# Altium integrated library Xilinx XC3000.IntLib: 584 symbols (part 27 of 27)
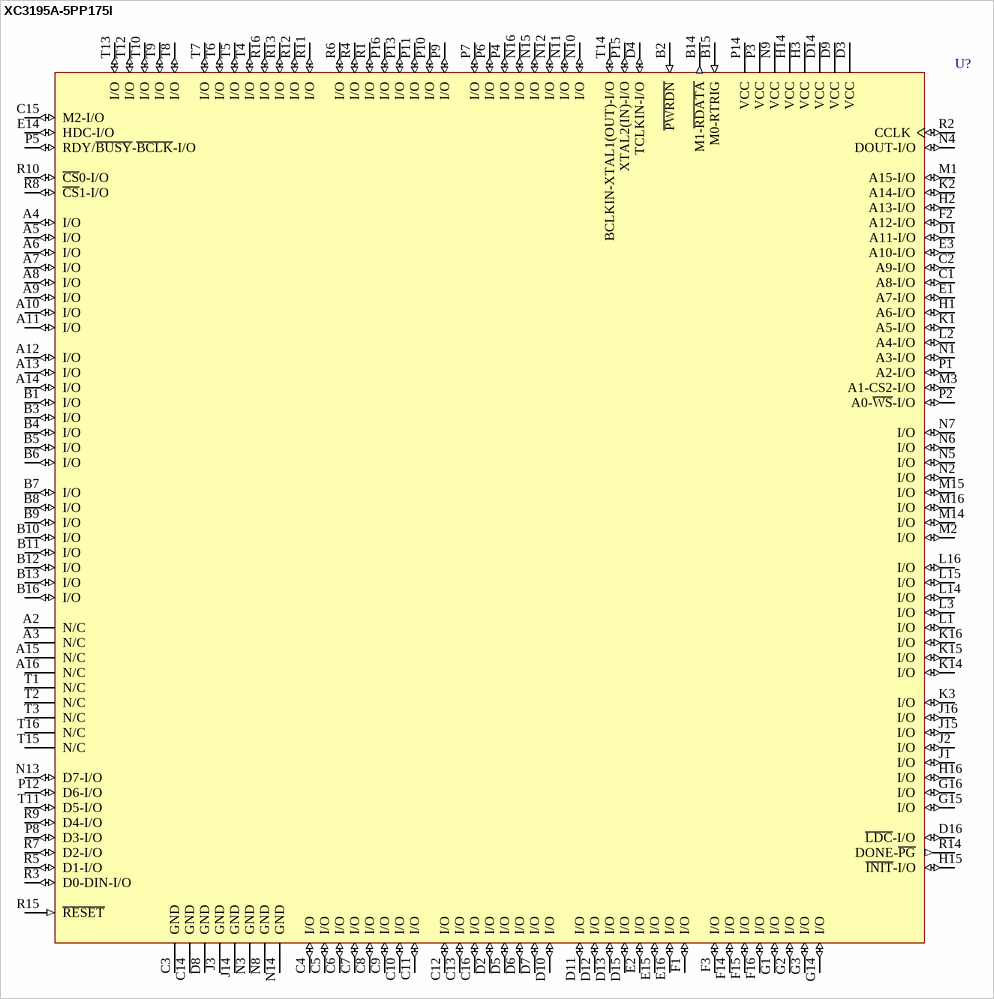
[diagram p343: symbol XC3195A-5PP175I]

## XC3195A-5PP175I
designator U?
Logic Cell Array with 484 CLBs, with 144 I/O Pins, 175-Pin PGA, Industrial Grade; ComponentAvailability: Not for New Design
footprint PP175 (PGA, 175-Leads, Body 42x42mm, Pitch 2.54mm)
3D model XC3195A-PP175 (175-Pin Plastic Pin Grid Array (PP175))
pins: A2 N/C, A3 N/C, A4 I/O (io), A5 I/O (io), A6 I/O (io), A7 I/O (io), A8 I/O (io), A9 I/O (io), A10 I/O (io), A11 I/O (io), A12 I/O (io), A13 I/O (io), A14 I/O (io), A15 N/C, A16 N/C, B1 I/O (io), B2 ~{PWRDN} (in), B3 I/O (io), B4 I/O (io), B5 I/O (io), B6 I/O (io), B7 I/O (io), B8 I/O (io), B9 I/O (io), B10 I/O (io), B11 I/O (io), B12 I/O (io), B13 I/O (io), B14 M1-~{RDATA} (out), B15 M0-RTRIG (in), B16 I/O (io), C1 A8-I/O (io), C2 A9-I/O (io), C3 GND (power), C4 I/O (io), C5 I/O (io), C6 I/O (io), C7 I/O (io), C8 I/O (io), C9 I/O (io), C10 I/O (io), C11 I/O (io), C12 I/O (io), C13 I/O (io), C14 GND (power), C15 M2-I/O (io), C16 I/O (io), D1 A11-I/O (io), D2 I/O (io), D3 VCC (power), D4 TCLKIN-I/O (io), D5 I/O (io), D6 I/O (io), D7 I/O (io), D8 GND (power), D9 VCC (power), D10 I/O (io), D11 I/O (io), D12 I/O (io), D13 I/O (io), D14 VCC (power), D15 I/O (io), D16 ~{LDC}-I/O (io), E1 A7-I/O (io), E2 I/O (io), E3 A10-I/O (io), E14 HDC-I/O (io), E15 I/O (io), E16 I/O (io), F1 I/O (io), F2 A12-I/O (io), F3 I/O (io), F14 I/O (io), F15 I/O (io), F16 I/O (io), G1 I/O (io), G2 I/O (io), G3 I/O (io), G14 I/O (io), G15 I/O (io), G16 I/O (io), H1 A6-I/O (io), H2 A13-I/O (io), H3 VCC (power), H14 VCC (power), H15 ~{INIT}-I/O (io), H16 I/O (io), J1 I/O (io), J2 I/O (io), J3 GND (power), J14 GND (power), J15 I/O (io), J16 I/O (io), K1 A5-I/O (io), K2 A14-I/O (io), K3 I/O (io), K14 I/O (io), K15 I/O (io), K16 I/O (io), L1 I/O (io), L2 A4-I/O (io), L3 I/O (io), L14 I/O (io), L15 I/O (io), L16 I/O (io), M1 A15-I/O (io), M2 I/O (io), M3 A1-CS2-I/O (io), M14 I/O (io), M15 I/O (io), M16 I/O (io), N1 A3-I/O (io), N2 I/O (io), N3 GND (power), N4 DOUT-I/O (io), N5 I/O (io), N6 I/O (io), N7 I/O (io), N8 GND (power), N9 VCC (power), N10 I/O (io), N11 I/O (io), N12 I/O (io), N13 D7-I/O (io), N14 GND (power), N15 I/O (io), N16 I/O (io), P1 A2-I/O (io), P2 A0-~{WS}-I/O (io), P3 VCC (power), P4 I/O (io), P5 RDY/~{BUSY}-~{BCLK}-I/O (io), P6 I/O (io), P7 I/O (io), P8 D3-I/O (io), P9 I/O (io), P10 I/O (io), P11 I/O (io), P12 D6-I/O (io), P13 I/O (io), P14 VCC (power), P15 XTAL2(IN)-I/O (io), P16 I/O (io), R1 I/O (io), R2 CCLK (io), R3 D0-DIN-I/O (io), R4 I/O (io), R5 D1-I/O (io), R6 I/O (io), R7 D2-I/O (io), R8 ~{CS}1-I/O (io), R9 D4-I/O (io), R10 ~{CS}0-I/O (io), R11 I/O (io), R12 I/O (io), R13 I/O (io), R14 DONE-~{PG} (out), R15 ~{RESET} (in), R16 I/O (io), T1 N/C, T2 N/C, T3 N/C, T4 I/O (io), T5 I/O (io), T6 I/O (io), T7 I/O (io), T8 I/O (io), T9 I/O (io), T10 I/O (io), T11 D5-I/O (io), T12 I/O (io), T13 I/O (io), T14 BCLKIN-XTAL1(OUT)-I/O (io), T15 N/C, T16 N/C

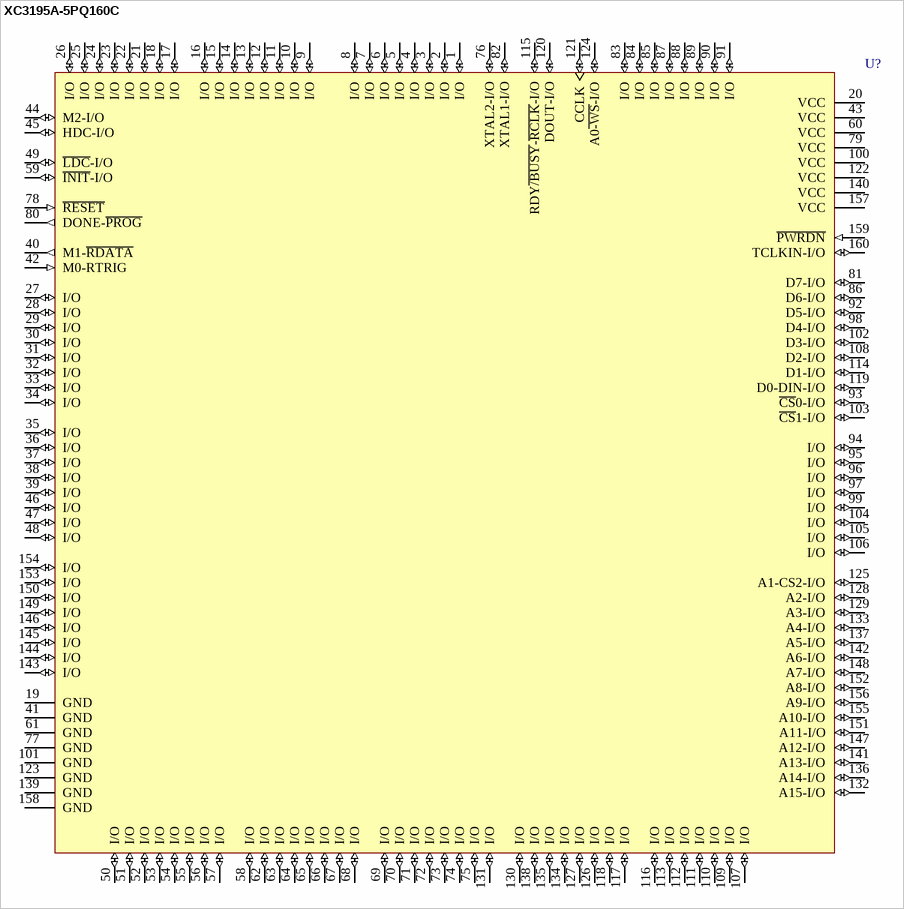
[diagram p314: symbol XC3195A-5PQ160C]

## XC3195A-5PQ160C
designator U?
Logic Cell Array with 484 CLBs, with 138 I/O Pins, 160-Pin PQFP, Commercial Grade; ComponentAvailability: Not for New Design
footprint PQ160_N (QFP, 160-Leads, Body 28 x 28mm, Pitch 0.65mm, IPC Medium Density)
footprint PQ160_L (QFP, 160-Leads, Body 28 x 28mm, Pitch 0.65mm, IPC High Density)
footprint PQ160_M (QFP, 160-Leads, Body 28 x 28mm, Pitch 0.65mm, IPC Low Density)
3D model XC3195A-PQ160 (160-Pin Plastic Quad Flat Pack (PQ160))
pins: 1 I/O (io), 2 I/O (io), 3 I/O (io), 4 I/O (io), 5 I/O (io), 6 I/O (io), 7 I/O (io), 8 I/O (io), 9 I/O (io), 10 I/O (io), 11 I/O (io), 12 I/O (io), 13 I/O (io), 14 I/O (io), 15 I/O (io), 16 I/O (io), 17 I/O (io), 18 I/O (io), 19 GND (power), 20 VCC (power), 21 I/O (io), 22 I/O (io), 23 I/O (io), 24 I/O (io), 25 I/O (io), 26 I/O (io), 27 I/O (io), 28 I/O (io), 29 I/O (io), 30 I/O (io), 31 I/O (io), 32 I/O (io), 33 I/O (io), 34 I/O (io), 35 I/O (io), 36 I/O (io), 37 I/O (io), 38 I/O (io), 39 I/O (io), 40 M1-~{RDATA} (out), 41 GND (power), 42 M0-RTRIG (in), 43 VCC (power), 44 M2-I/O (io), 45 HDC-I/O (io), 46 I/O (io), 47 I/O (io), 48 I/O (io), 49 ~{LDC}-I/O (io), 50 I/O (io), 51 I/O (io), 52 I/O (io), 53 I/O (io), 54 I/O (io), 55 I/O (io), 56 I/O (io), 57 I/O (io), 58 I/O (io), 59 ~{INIT}-I/O (io), 60 VCC (power), 61 GND (power), 62 I/O (io), 63 I/O (io), 64 I/O (io), 65 I/O (io), 66 I/O (io), 67 I/O (io), 68 I/O (io), 69 I/O (io), 70 I/O (io), 71 I/O (io), 72 I/O (io), 73 I/O (io), 74 I/O (io), 75 I/O (io), 76 XTAL2-I/O (io), 77 GND (power), 78 ~{RESET} (in), 79 VCC (power), 80 DONE-~{PROG} (out), 81 D7-I/O (io), 82 XTAL1-I/O (io), 83 I/O (io), 84 I/O (io), 85 I/O (io), 86 D6-I/O (io), 87 I/O (io), 88 I/O (io), 89 I/O (io), 90 I/O (io), 91 I/O (io), 92 D5-I/O (io), 93 ~{CS}0-I/O (io), 94 I/O (io), 95 I/O (io), 96 I/O (io), 97 I/O (io), 98 D4-I/O (io), 99 I/O (io), 100 VCC (power), 101 GND (power), 102 D3-I/O (io), 103 ~{CS}1-I/O (io), 104 I/O (io), 105 I/O (io), 106 I/O (io), 107 I/O (io), 108 D2-I/O (io), 109 I/O (io), 110 I/O (io), 111 I/O (io), 112 I/O (io), 113 I/O (io), 114 D1-I/O (io), 115 RDY~{/BUSY}-~{RCLK}-I/O (io), 116 I/O (io), 117 I/O (io), 118 I/O (io), 119 D0-DIN-I/O (io), 120 DOUT-I/O (io), 121 CCLK (io), 122 VCC (power), 123 GND (power), 124 A0~{-WS}-I/O (io), 125 A1-CS2-I/O (io), 126 I/O (io), 127 I/O (io), 128 A2-I/O (io), 129 A3-I/O (io), 130 I/O (io), 131 I/O (io), 132 A15-I/O (io), 133 A4-I/O (io), 134 I/O (io), 135 I/O (io), 136 A14-I/O (io), 137 A5-I/O (io), 138 I/O (io), 139 GND (power), 140 VCC (power), 141 A13-I/O (io), 142 A6-I/O (io), 143 I/O (io), 144 I/O (io), 145 I/O (io), 146 I/O (io), 147 A12-I/O (io), 148 A7-I/O (io), 149 I/O (io), 150 I/O (io), 151 A11-I/O (io), 152 A8-I/O (io), 153 I/O (io), 154 I/O (io), 155 A10-I/O (io), 156 A9-I/O (io), 157 VCC (power), 158 GND (power), 159 ~{PWRDN} (in), 160 TCLKIN-I/O (io)

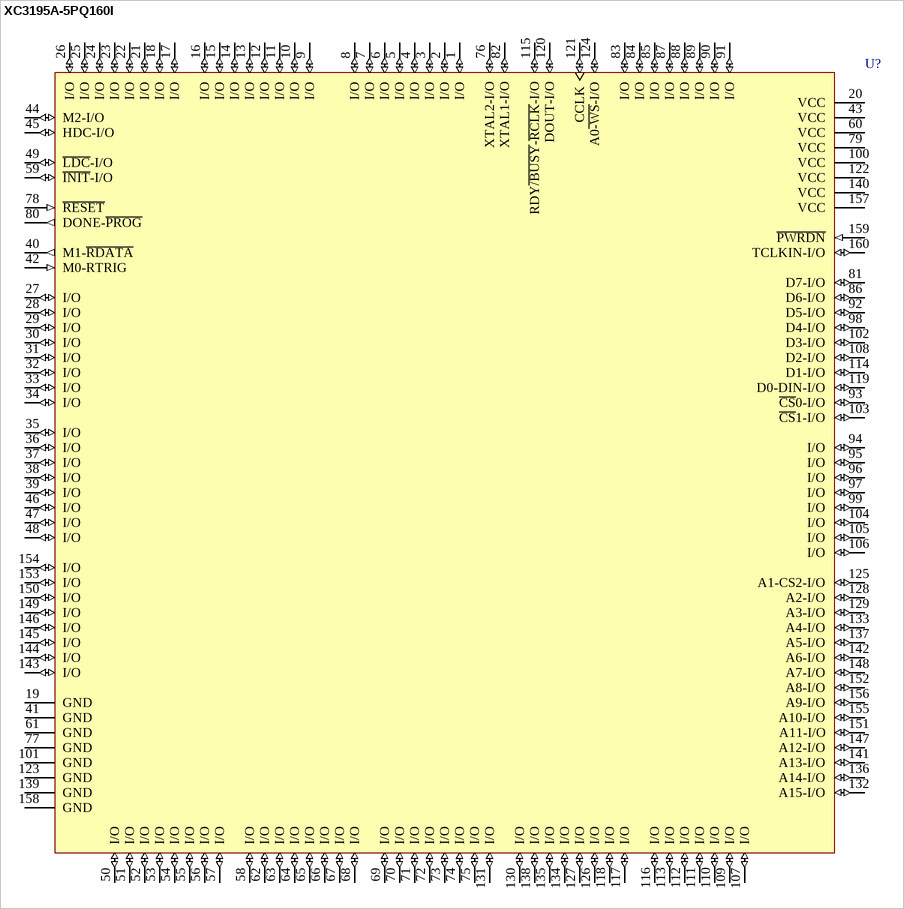
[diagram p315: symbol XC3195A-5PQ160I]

## XC3195A-5PQ160I
designator U?
Logic Cell Array with 484 CLBs, with 138 I/O Pins, 160-Pin PQFP, Industrial Grade; ComponentAvailability: Not for New Design
footprint PQ160_N (QFP, 160-Leads, Body 28 x 28mm, Pitch 0.65mm, IPC Medium Density)
footprint PQ160_L (QFP, 160-Leads, Body 28 x 28mm, Pitch 0.65mm, IPC High Density)
footprint PQ160_M (QFP, 160-Leads, Body 28 x 28mm, Pitch 0.65mm, IPC Low Density)
3D model XC3195A-PQ160 (160-Pin Plastic Quad Flat Pack (PQ160))
pins: 1 I/O (io), 2 I/O (io), 3 I/O (io), 4 I/O (io), 5 I/O (io), 6 I/O (io), 7 I/O (io), 8 I/O (io), 9 I/O (io), 10 I/O (io), 11 I/O (io), 12 I/O (io), 13 I/O (io), 14 I/O (io), 15 I/O (io), 16 I/O (io), 17 I/O (io), 18 I/O (io), 19 GND (power), 20 VCC (power), 21 I/O (io), 22 I/O (io), 23 I/O (io), 24 I/O (io), 25 I/O (io), 26 I/O (io), 27 I/O (io), 28 I/O (io), 29 I/O (io), 30 I/O (io), 31 I/O (io), 32 I/O (io), 33 I/O (io), 34 I/O (io), 35 I/O (io), 36 I/O (io), 37 I/O (io), 38 I/O (io), 39 I/O (io), 40 M1-~{RDATA} (out), 41 GND (power), 42 M0-RTRIG (in), 43 VCC (power), 44 M2-I/O (io), 45 HDC-I/O (io), 46 I/O (io), 47 I/O (io), 48 I/O (io), 49 ~{LDC}-I/O (io), 50 I/O (io), 51 I/O (io), 52 I/O (io), 53 I/O (io), 54 I/O (io), 55 I/O (io), 56 I/O (io), 57 I/O (io), 58 I/O (io), 59 ~{INIT}-I/O (io), 60 VCC (power), 61 GND (power), 62 I/O (io), 63 I/O (io), 64 I/O (io), 65 I/O (io), 66 I/O (io), 67 I/O (io), 68 I/O (io), 69 I/O (io), 70 I/O (io), 71 I/O (io), 72 I/O (io), 73 I/O (io), 74 I/O (io), 75 I/O (io), 76 XTAL2-I/O (io), 77 GND (power), 78 ~{RESET} (in), 79 VCC (power), 80 DONE-~{PROG} (out), 81 D7-I/O (io), 82 XTAL1-I/O (io), 83 I/O (io), 84 I/O (io), 85 I/O (io), 86 D6-I/O (io), 87 I/O (io), 88 I/O (io), 89 I/O (io), 90 I/O (io), 91 I/O (io), 92 D5-I/O (io), 93 ~{CS}0-I/O (io), 94 I/O (io), 95 I/O (io), 96 I/O (io), 97 I/O (io), 98 D4-I/O (io), 99 I/O (io), 100 VCC (power), 101 GND (power), 102 D3-I/O (io), 103 ~{CS}1-I/O (io), 104 I/O (io), 105 I/O (io), 106 I/O (io), 107 I/O (io), 108 D2-I/O (io), 109 I/O (io), 110 I/O (io), 111 I/O (io), 112 I/O (io), 113 I/O (io), 114 D1-I/O (io), 115 RDY~{/BUSY}-~{RCLK}-I/O (io), 116 I/O (io), 117 I/O (io), 118 I/O (io), 119 D0-DIN-I/O (io), 120 DOUT-I/O (io), 121 CCLK (io), 122 VCC (power), 123 GND (power), 124 A0~{-WS}-I/O (io), 125 A1-CS2-I/O (io), 126 I/O (io), 127 I/O (io), 128 A2-I/O (io), 129 A3-I/O (io), 130 I/O (io), 131 I/O (io), 132 A15-I/O (io), 133 A4-I/O (io), 134 I/O (io), 135 I/O (io), 136 A14-I/O (io), 137 A5-I/O (io), 138 I/O (io), 139 GND (power), 140 VCC (power), 141 A13-I/O (io), 142 A6-I/O (io), 143 I/O (io), 144 I/O (io), 145 I/O (io), 146 I/O (io), 147 A12-I/O (io), 148 A7-I/O (io), 149 I/O (io), 150 I/O (io), 151 A11-I/O (io), 152 A8-I/O (io), 153 I/O (io), 154 I/O (io), 155 A10-I/O (io), 156 A9-I/O (io), 157 VCC (power), 158 GND (power), 159 ~{PWRDN} (in), 160 TCLKIN-I/O (io)

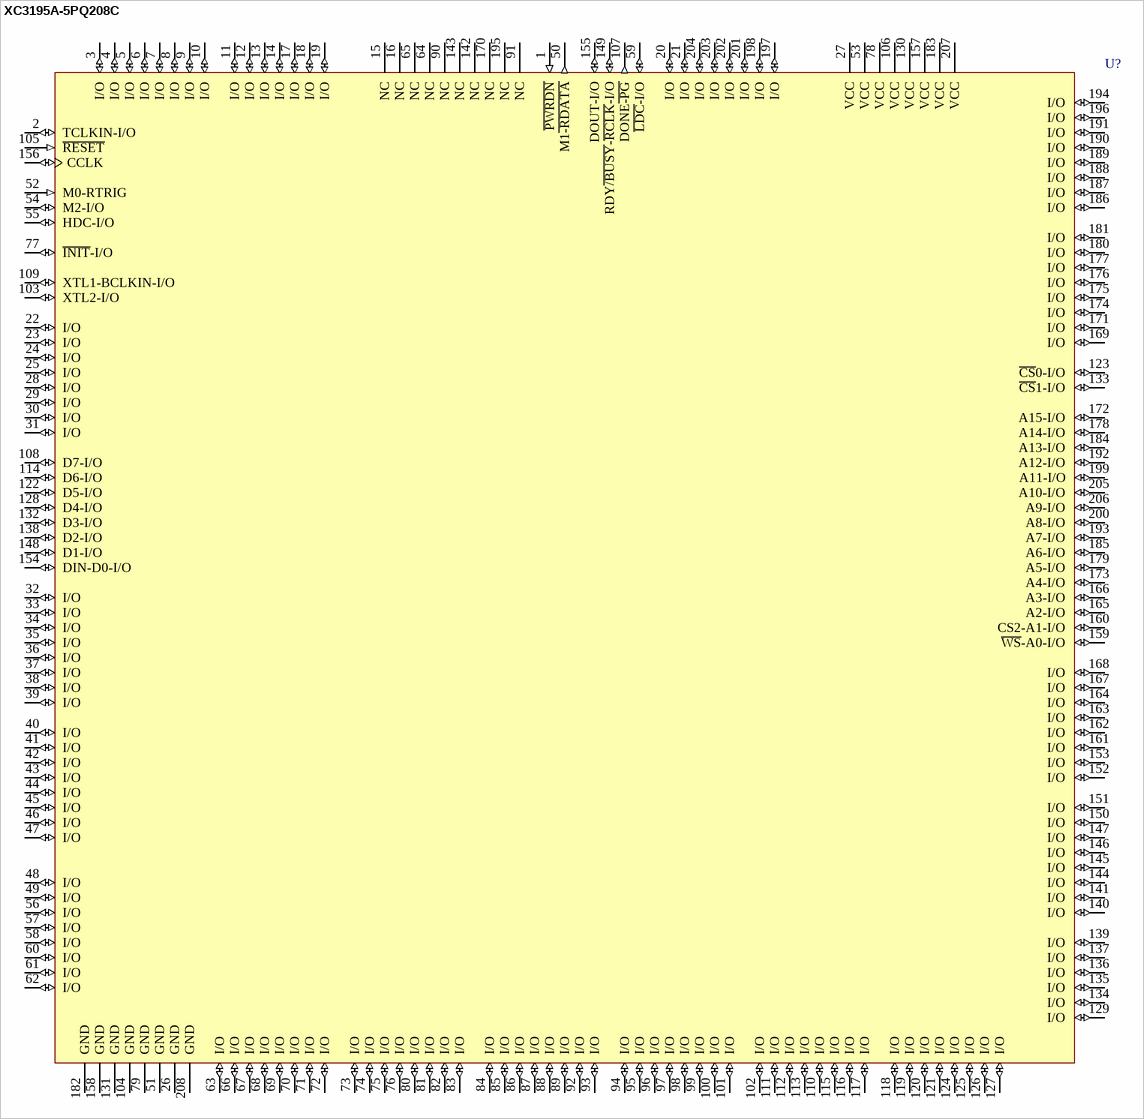
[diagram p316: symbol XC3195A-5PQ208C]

## XC3195A-5PQ208C
designator U?
Logic Cell Array with 484 CLBs, with 176 I/O Pins, 208-Pin PQFP, Commercial Grade; ComponentAvailability: Not for New Design
footprint PQ208_N (Shrink QFP, 208-Leads, Body 28x28mm, Pitch 0.5mm, IPC Medium Density)
footprint PQ208_L (Shrink QFP, 208-Leads, Body 28x28mm, Pitch 0.5mm, IPC High Density)
footprint PQ208_M (Shrink QFP, 208-Leads, Body 28x28mm, Pitch 0.5mm, IPC Low Density)
3D model XC3195A-PQ208 (208-Pin Plastic Quad Flat Pack (PQ208))
pins: 1 ~{PWRDN} (in), 2 TCLKIN-I/O (io), 3 I/O (io), 4 I/O (io), 5 I/O (io), 6 I/O (io), 7 I/O (io), 8 I/O (io), 9 I/O (io), 10 I/O (io), 11 I/O (io), 12 I/O (io), 13 I/O (io), 14 I/O (io), 15 NC, 16 NC, 17 I/O (io), 18 I/O (io), 19 I/O (io), 20 I/O (io), 21 I/O (io), 22 I/O (io), 23 I/O (io), 24 I/O (io), 25 I/O (io), 26 GND (power), 27 VCC (power), 28 I/O (io), 29 I/O (io), 30 I/O (io), 31 I/O (io), 32 I/O (io), 33 I/O (io), 34 I/O (io), 35 I/O (io), 36 I/O (io), 37 I/O (io), 38 I/O (io), 39 I/O (io), 40 I/O (io), 41 I/O (io), 42 I/O (io), 43 I/O (io), 44 I/O (io), 45 I/O (io), 46 I/O (io), 47 I/O (io), 48 I/O (io), 49 I/O (io), 50 M1~{-RDATA} (out), 51 GND (power), 52 M0-RTRIG (in), 53 VCC (power), 54 M2-I/O (io), 55 HDC-I/O (io), 56 I/O (io), 57 I/O (io), 58 I/O (io), 59 ~{LDC}-I/O (io), 60 I/O (io), 61 I/O (io), 62 I/O (io), 63 I/O (io), 64 NC, 65 NC, 66 I/O (io), 67 I/O (io), 68 I/O (io), 69 I/O (io), 70 I/O (io), 71 I/O (io), 72 I/O (io), 73 I/O (io), 74 I/O (io), 75 I/O (io), 76 I/O (io), 77 ~{INIT}-I/O (io), 78 VCC (power), 79 GND (power), 80 I/O (io), 81 I/O (io), 82 I/O (io), 83 I/O (io), 84 I/O (io), 85 I/O (io), 86 I/O (io), 87 I/O (io), 88 I/O (io), 89 I/O (io), 90 NC, 91 NC, 92 I/O (io), 93 I/O (io), 94 I/O (io), 95 I/O (io), 96 I/O (io), 97 I/O (io), 98 I/O (io), 99 I/O (io), 100 I/O (io), 101 I/O (io), 102 I/O (io), 103 XTL2-I/O (io), 104 GND (power), 105 ~{RESET} (in), 106 VCC (power), 107 DONE~{-PG} (out), 108 D7-I/O (io), 109 XTL1-BCLKIN-I/O (io), 110 I/O (io), 111 I/O (io), 112 I/O (io), 113 I/O (io), 114 D6-I/O (io), 115 I/O (io), 116 I/O (io), 117 I/O (io), 118 I/O (io), 119 I/O (io), 120 I/O (io), 121 I/O (io), 122 D5-I/O (io), 123 ~{CS}0-I/O (io), 124 I/O (io), 125 I/O (io), 126 I/O (io), 127 I/O (io), 128 D4-I/O (io), 129 I/O (io), 130 VCC (power), 131 GND (power), 132 D3-I/O (io), 133 ~{CS}1-I/O (io), 134 I/O (io), 135 I/O (io), 136 I/O (io), 137 I/O (io), 138 D2-I/O (io), 139 I/O (io), 140 I/O (io), 141 I/O (io), 142 NC, 143 NC, 144 I/O (io), 145 I/O (io), 146 I/O (io), 147 I/O (io), 148 D1-I/O (io), 149 RDY~{/BUSY}-~{RCLK}-I/O (io), 150 I/O (io), 151 I/O (io), 152 I/O (io), 153 I/O (io), 154 DIN-D0-I/O (io), 155 DOUT-I/O (io), 156 CCLK (io), 157 VCC (power), 158 GND (power), 159 ~{WS}-A0-I/O (io), 160 CS2-A1-I/O (io), 161 I/O (io), 162 I/O (io), 163 I/O (io), 164 I/O (io), 165 A2-I/O (io), 166 A3-I/O (io), 167 I/O (io), 168 I/O (io), 169 I/O (io), 170 NC, 171 I/O (io), 172 A15-I/O (io), 173 A4-I/O (io), 174 I/O (io), 175 I/O (io), 176 I/O (io), 177 I/O (io), 178 A14-I/O (io), 179 A5-I/O (io), 180 I/O (io), 181 I/O (io), 182 GND (power), 183 VCC (power), 184 A13-I/O (io), 185 A6-I/O (io), 186 I/O (io), 187 I/O (io), 188 I/O (io), 189 I/O (io), 190 I/O (io), 191 I/O (io), 192 A12-I/O (io), 193 A7-I/O (io), 194 I/O (io), 195 NC, 196 I/O (io), 197 I/O (io), 198 I/O (io), 199 A11-I/O (io), 200 A8-I/O (io), 201 I/O (io), 202 I/O (io), 203 I/O (io), 204 I/O (io), 205 A10-I/O (io), 206 A9-I/O (io), 207 VCC (power), 208 GND (power)

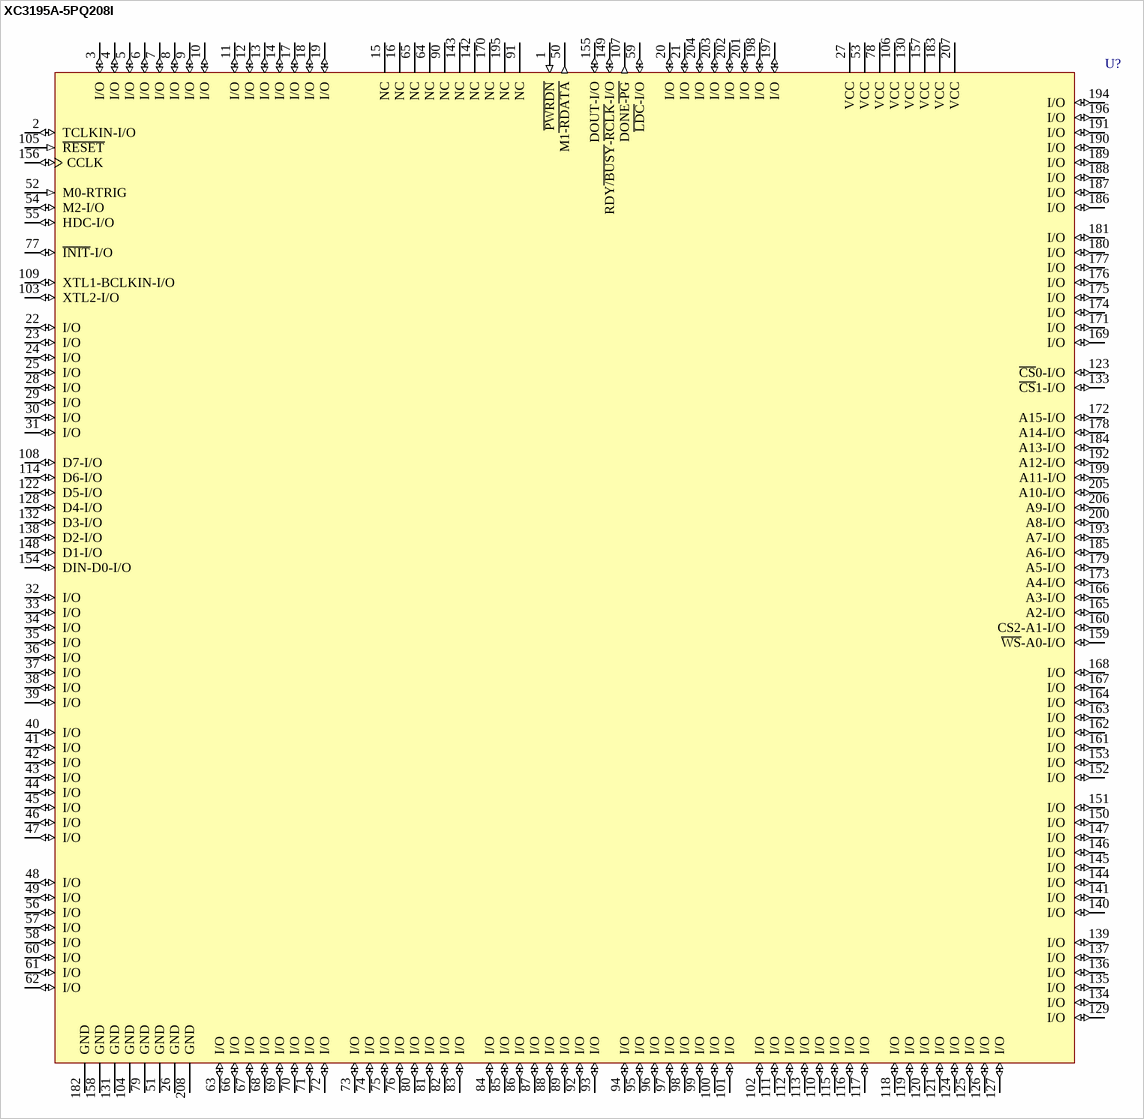
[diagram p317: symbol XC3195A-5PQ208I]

## XC3195A-5PQ208I
designator U?
Logic Cell Array with 484 CLBs, with 176 I/O Pins, 208-Pin PQFP, Industrial Grade; ComponentAvailability: Not for New Design
footprint PQ208_N (Shrink QFP, 208-Leads, Body 28x28mm, Pitch 0.5mm, IPC Medium Density)
footprint PQ208_L (Shrink QFP, 208-Leads, Body 28x28mm, Pitch 0.5mm, IPC High Density)
footprint PQ208_M (Shrink QFP, 208-Leads, Body 28x28mm, Pitch 0.5mm, IPC Low Density)
3D model XC3195A-PQ208 (208-Pin Plastic Quad Flat Pack (PQ208))
pins: 1 ~{PWRDN} (in), 2 TCLKIN-I/O (io), 3 I/O (io), 4 I/O (io), 5 I/O (io), 6 I/O (io), 7 I/O (io), 8 I/O (io), 9 I/O (io), 10 I/O (io), 11 I/O (io), 12 I/O (io), 13 I/O (io), 14 I/O (io), 15 NC, 16 NC, 17 I/O (io), 18 I/O (io), 19 I/O (io), 20 I/O (io), 21 I/O (io), 22 I/O (io), 23 I/O (io), 24 I/O (io), 25 I/O (io), 26 GND (power), 27 VCC (power), 28 I/O (io), 29 I/O (io), 30 I/O (io), 31 I/O (io), 32 I/O (io), 33 I/O (io), 34 I/O (io), 35 I/O (io), 36 I/O (io), 37 I/O (io), 38 I/O (io), 39 I/O (io), 40 I/O (io), 41 I/O (io), 42 I/O (io), 43 I/O (io), 44 I/O (io), 45 I/O (io), 46 I/O (io), 47 I/O (io), 48 I/O (io), 49 I/O (io), 50 M1~{-RDATA} (out), 51 GND (power), 52 M0-RTRIG (in), 53 VCC (power), 54 M2-I/O (io), 55 HDC-I/O (io), 56 I/O (io), 57 I/O (io), 58 I/O (io), 59 ~{LDC}-I/O (io), 60 I/O (io), 61 I/O (io), 62 I/O (io), 63 I/O (io), 64 NC, 65 NC, 66 I/O (io), 67 I/O (io), 68 I/O (io), 69 I/O (io), 70 I/O (io), 71 I/O (io), 72 I/O (io), 73 I/O (io), 74 I/O (io), 75 I/O (io), 76 I/O (io), 77 ~{INIT}-I/O (io), 78 VCC (power), 79 GND (power), 80 I/O (io), 81 I/O (io), 82 I/O (io), 83 I/O (io), 84 I/O (io), 85 I/O (io), 86 I/O (io), 87 I/O (io), 88 I/O (io), 89 I/O (io), 90 NC, 91 NC, 92 I/O (io), 93 I/O (io), 94 I/O (io), 95 I/O (io), 96 I/O (io), 97 I/O (io), 98 I/O (io), 99 I/O (io), 100 I/O (io), 101 I/O (io), 102 I/O (io), 103 XTL2-I/O (io), 104 GND (power), 105 ~{RESET} (in), 106 VCC (power), 107 DONE~{-PG} (out), 108 D7-I/O (io), 109 XTL1-BCLKIN-I/O (io), 110 I/O (io), 111 I/O (io), 112 I/O (io), 113 I/O (io), 114 D6-I/O (io), 115 I/O (io), 116 I/O (io), 117 I/O (io), 118 I/O (io), 119 I/O (io), 120 I/O (io), 121 I/O (io), 122 D5-I/O (io), 123 ~{CS}0-I/O (io), 124 I/O (io), 125 I/O (io), 126 I/O (io), 127 I/O (io), 128 D4-I/O (io), 129 I/O (io), 130 VCC (power), 131 GND (power), 132 D3-I/O (io), 133 ~{CS}1-I/O (io), 134 I/O (io), 135 I/O (io), 136 I/O (io), 137 I/O (io), 138 D2-I/O (io), 139 I/O (io), 140 I/O (io), 141 I/O (io), 142 NC, 143 NC, 144 I/O (io), 145 I/O (io), 146 I/O (io), 147 I/O (io), 148 D1-I/O (io), 149 RDY~{/BUSY}-~{RCLK}-I/O (io), 150 I/O (io), 151 I/O (io), 152 I/O (io), 153 I/O (io), 154 DIN-D0-I/O (io), 155 DOUT-I/O (io), 156 CCLK (io), 157 VCC (power), 158 GND (power), 159 ~{WS}-A0-I/O (io), 160 CS2-A1-I/O (io), 161 I/O (io), 162 I/O (io), 163 I/O (io), 164 I/O (io), 165 A2-I/O (io), 166 A3-I/O (io), 167 I/O (io), 168 I/O (io), 169 I/O (io), 170 NC, 171 I/O (io), 172 A15-I/O (io), 173 A4-I/O (io), 174 I/O (io), 175 I/O (io), 176 I/O (io), 177 I/O (io), 178 A14-I/O (io), 179 A5-I/O (io), 180 I/O (io), 181 I/O (io), 182 GND (power), 183 VCC (power), 184 A13-I/O (io), 185 A6-I/O (io), 186 I/O (io), 187 I/O (io), 188 I/O (io), 189 I/O (io), 190 I/O (io), 191 I/O (io), 192 A12-I/O (io), 193 A7-I/O (io), 194 I/O (io), 195 NC, 196 I/O (io), 197 I/O (io), 198 I/O (io), 199 A11-I/O (io), 200 A8-I/O (io), 201 I/O (io), 202 I/O (io), 203 I/O (io), 204 I/O (io), 205 A10-I/O (io), 206 A9-I/O (io), 207 VCC (power), 208 GND (power)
